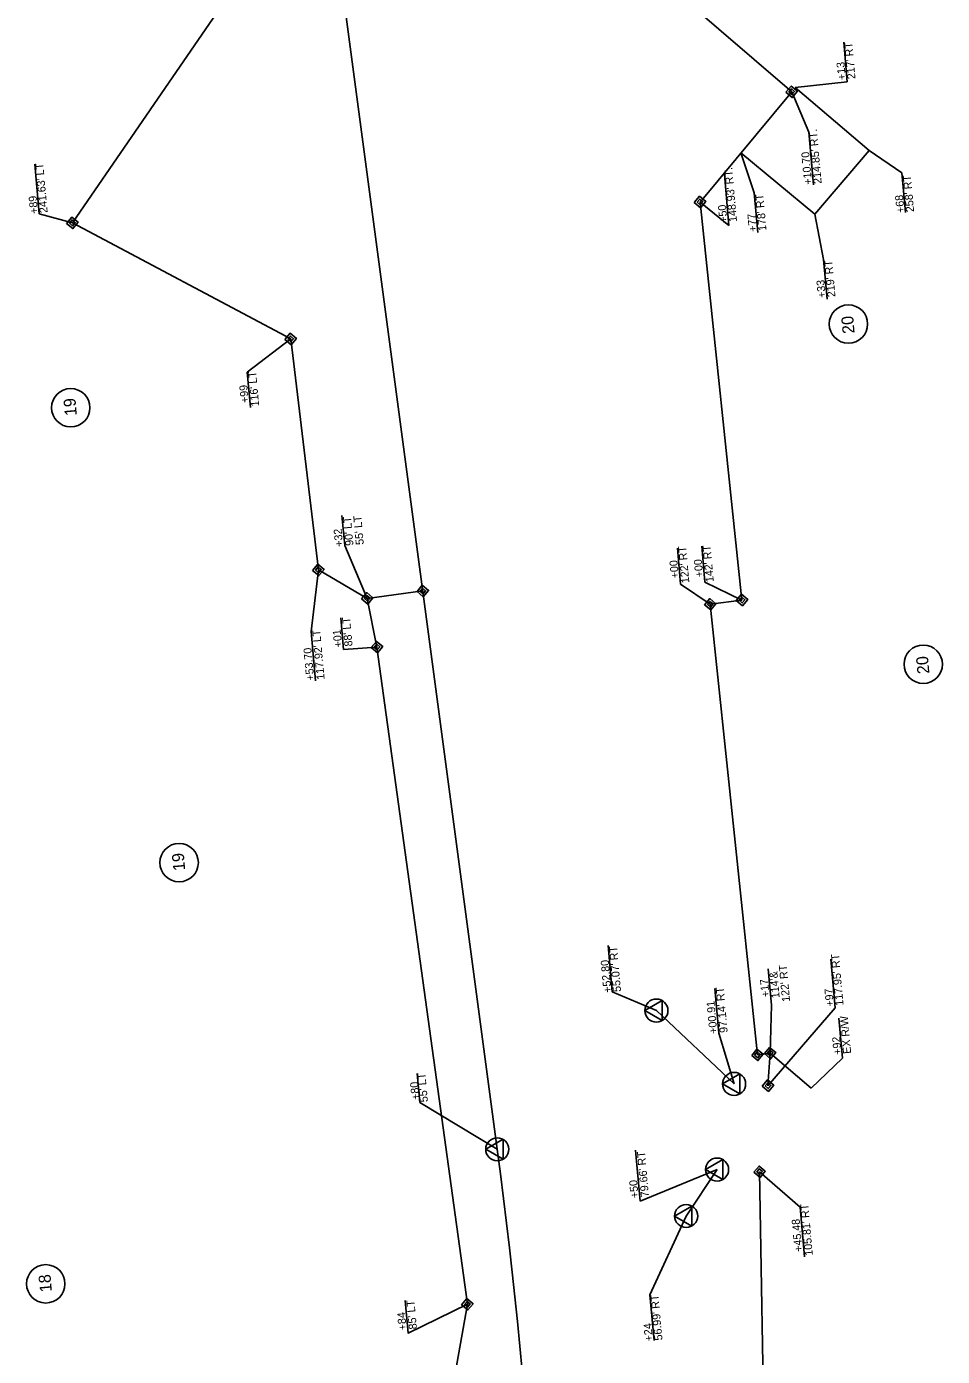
# Model space of a CAD drawing. Extents: x 1555582 to 1558054, y 687961 to 694065.
# Drawn here: x 1555788 to 1556360, y 692503 to 693334 of the extents above; entities that cross this region are included whole.
import ezdxf

# ---------------------------------------------------------------- set-up
doc = ezdxf.new("R2010")
doc.units = 0
for name, color, linetype in [('Exist Horizontal Alignment', 7, 'Continuous'), ('Exist Hydrographic FEMA Cross Section', 7, 'Continuous'), ('Exist Structure Minor Drop Inlet Text', 7, 'Continuous'), ('Prop Approach Slab', 7, 'Continuous'), ('Prop Approach Slab Hatching', 7, 'Continuous'), ('Prop Boundary Easement Temporary Drainage Label', 7, 'Continuous'), ('Prop Drainage Structure Box Reinforced Concrete', 7, 'Continuous'), ('Prop Drainage Structure Bridge', 7, 'Continuous'), ('Prop Drainage Structure Catch Basin Grate 840 03F Label', 7, 'Continuous'), ('Prop Drainage Structure Catch Basin Grate 840 03G CELL', 7, 'Continuous'), ('Prop Drainage Structure Plot Symbol 50 Scale', 7, 'Continuous'), ('Prop Plan Preparation Excavation Hatching', 7, 'Continuous'), ('Scratch_Level_3', 7, 'Continuous')]:
    doc.layers.add(name, color=color, linetype=linetype)

msp = doc.modelspace()

# ---------------------------------------------------------------- linework, layer by layer
at = {"layer": 'Exist Horizontal Alignment'}
for p, q in [((1556150.96, 692759.72), (1556153.56, 692730.83)), ((1556217.7, 692732.91), (1556220.21, 692705.02)), ((1556220.21, 692705.02), (1556229.73, 692673.27)), ((1556031.71, 692679.8), (1556033.35, 692661.64)), ((1556033.35, 692661.64), (1556081.7, 692632.42)), ((1556219.1, 692619.76), (1556171.02, 692599.96)), ((1556177.13, 692541.4), (1556179.69, 692513.01))]:
    msp.add_line(p, q, dxfattribs=at)
for points in [[(1556153.56, 692730.83), (1556181.17, 692719.14)], [(1556171.02, 692599.96), (1556168.15, 692631.83)], [(1556177.13, 692541.4), (1556199.76, 692590.71)]]:
    msp.add_lwpolyline(points, dxfattribs=at)
at = {"layer": 'Exist Hydrographic FEMA Cross Section'}
for p, q in [((1556081.7, 692632.42), (1555947.69, 693636.52)), ((1556229.73, 692673.27), (1556181.17, 692719.14)), ((1556199.76, 692590.71), (1556219.1, 692619.76))]:
    msp.add_line(p, q, dxfattribs=at)
msp.add_arc((1552867.37, 692203.31), 3242.85, 358.84759, 7.60403, dxfattribs=at)
at = {"layer": 'Exist Structure Minor Drop Inlet Text'}
for p, q in [((1556298.25, 693324.37), (1556300.48, 693299.56)), ((1556242.35, 693230.05), (1556233.92, 693255.03)), ((1556334.58, 693242.69), (1556336.82, 693217.88)), ((1556242.35, 693230.05), (1556244.58, 693205.24)), ((1556285.65, 693188.43), (1556287.88, 693163.62)), ((1556295.2, 692714.27), (1556297.43, 692689.46))]:
    msp.add_line(p, q, dxfattribs=at)
for points in [[(1556300.48, 693299.56), (1556267.91, 693295.89)], [(1556334.58, 693242.69), (1556314.16, 693256.66)], [(1556285.65, 693188.43), (1556280.13, 693216.81)], [(1556297.43, 692689.46), (1556277.96, 692670.72)]]:
    msp.add_lwpolyline(points, dxfattribs=at)
at = {"layer": 'Prop Approach Slab'}
for p, q in [((1556035.13, 692981.33), (1556000.44, 692976.7)), ((1556006.52, 692946.24), (1556000.44, 692976.7)), ((1556062.99, 692535.58), (1556006.52, 692946.24)), ((1556048.4, 692453.34), (1556062.99, 692535.58))]:
    msp.add_line(p, q, dxfattribs=at)
at = {"layer": 'Prop Approach Slab Hatching'}
for p, q in [((1556265.74, 693293.28), (1556265.74, 693293.28)), ((1556208.43, 693224.39), (1556208.43, 693224.39)), ((1555816.15, 693211.38), (1555816.15, 693211.38)), ((1555952.58, 693138.79), (1555952.58, 693138.79)), ((1555969.89, 692994.52), (1555969.89, 692994.52)), ((1556000.44, 692976.7), (1556000.44, 692976.7)), ((1556035.13, 692981.33), (1556035.13, 692981.33)), ((1556234.64, 692975.67), (1556234.64, 692975.67)), ((1556214.81, 692973.03), (1556214.81, 692973.03)), ((1556006.52, 692946.24), (1556006.52, 692946.24)), ((1556244.32, 692691.46), (1556244.32, 692691.46)), ((1556252.25, 692692.51), (1556252.25, 692692.51)), ((1556250.89, 692672.15), (1556250.89, 692672.15)), ((1556245.63, 692618.36), (1556245.63, 692618.36)), ((1556062.99, 692535.58), (1556062.99, 692535.58))]:
    msp.add_line(p, q, dxfattribs=at)
at = {"layer": 'Prop Boundary Easement Temporary Drainage Label'}
for points in [[(1555983.9, 692964.51), (1555985.67, 692944.84), (1556006.52, 692946.24)], [(1556024.17, 692537.99), (1556026.01, 692517.52), (1556062.99, 692535.58)]]:
    msp.add_lwpolyline(points, dxfattribs=at)
at = {"layer": 'Prop Drainage Structure Box Reinforced Concrete'}
for p, q in [((1556314.16, 693256.66), (1556267.91, 693295.89)), ((1556280.13, 693216.81), (1556314.16, 693256.66)), ((1556280.13, 693216.81), (1556233.92, 693255.03))]:
    msp.add_line(p, q, dxfattribs=at)
msp.add_lwpolyline([(1556277.96, 692670.72), (1556252.25, 692692.51)], dxfattribs=at)
at = {"layer": 'Prop Drainage Structure Bridge'}
for q in [(1555984.65, 693028.46), (1556000.44, 692976.7)]:
    msp.add_line((1555986.44, 693009.64), q, dxfattribs=at)
at = {"layer": 'Prop Drainage Structure Catch Basin Grate 840 03F Label'}
for p, q in [((1556301.17, 693148.14), (1556301.17, 693148.14)), ((1555815.14, 693095.83), (1555815.14, 693095.83)), ((1556347.91, 692935.53), (1556347.91, 692935.53)), ((1555882.87, 692811.56), (1555882.87, 692811.56)), ((1555799.53, 692548.33), (1555799.53, 692548.33))]:
    msp.add_line(p, q, dxfattribs=at)
for centre in [(1556301.17, 693148.14), (1555815.14, 693095.83), (1556347.91, 692935.53), (1555882.87, 692811.56), (1555799.53, 692548.33)]:
    msp.add_circle(centre, 12, dxfattribs=at)
at = {"layer": 'Prop Drainage Structure Plot Symbol 50 Scale'}
for p, q in [((1556276.33, 693267.96), (1556279.29, 693235.09)), ((1555792.7, 693247.94), (1555795.48, 693217.06)), ((1556223.64, 693241.51), (1556226.5, 693209.64)), ((1555795.48, 693217.06), (1555816.15, 693211.38)), ((1555925.45, 693118.11), (1555952.58, 693138.79)), ((1555927.44, 693095.98), (1555925.45, 693118.11)), ((1556196.29, 692985.63), (1556194.26, 693008.12)), ((1556211.52, 692986.73), (1556209.48, 693009.32)), ((1556196.29, 692985.63), (1556214.81, 692973.03)), ((1556211.52, 692986.73), (1556234.64, 692975.67)), ((1556292.83, 692720.9), (1556290.1, 692751.28)), ((1556253.12, 692722.51), (1556251.08, 692745.2)), ((1556181.17, 692719.14), (1556181.17, 692719.14)), ((1556292.83, 692720.9), (1556250.89, 692672.15)), ((1556229.73, 692673.27), (1556229.73, 692673.27)), ((1556081.7, 692632.42), (1556081.7, 692632.42)), ((1556219.1, 692619.76), (1556219.1, 692619.76)), ((1556270.99, 692596.19), (1556245.63, 692618.36)), ((1556273.77, 692565.31), (1556270.99, 692596.19)), ((1556199.76, 692590.71), (1556199.76, 692590.71))]:
    msp.add_line(p, q, dxfattribs=at)
for points in [[(1556276.33, 693267.96), (1556265.74, 693293.28)], [(1556226.5, 693209.64), (1556208.43, 693224.39)], [(1555968.11, 692925.17), (1555965.33, 692956.05), (1555969.89, 692994.52)], [(1556253.12, 692722.51), (1556252.25, 692692.51)]]:
    msp.add_lwpolyline(points, dxfattribs=at)
for points in [[(1556184.76, 692712.89), (1556173.97, 692719.15), (1556184.78, 692725.39)], [(1556233.33, 692667.02), (1556222.53, 692673.28), (1556233.34, 692679.52)], [(1556085.29, 692626.17), (1556074.5, 692632.43), (1556085.31, 692638.67)], [(1556222.69, 692613.51), (1556211.9, 692619.77), (1556222.71, 692626.01)], [(1556203.35, 692584.46), (1556192.56, 692590.72), (1556203.37, 692596.96)]]:
    msp.add_lwpolyline(points, close=True, dxfattribs=at)
for centre in [(1556181.17, 692719.14), (1556229.73, 692673.27), (1556081.7, 692632.42), (1556219.1, 692619.76), (1556199.76, 692590.71)]:
    msp.add_circle(centre, 7.2, dxfattribs=at)
at = {"layer": 'Prop Plan Preparation Excavation Hatching'}
for p, q in [((1555816.15, 693211.38), (1555929.88, 693376.88)), ((1556265.74, 693293.28), (1556177.03, 693369.51)), ((1556208.43, 693224.39), (1556265.74, 693293.28)), ((1556234.64, 692975.67), (1556208.43, 693224.39)), ((1555952.58, 693138.79), (1555816.15, 693211.38)), ((1555969.89, 692994.52), (1555952.58, 693138.79)), ((1556000.44, 692976.7), (1555969.89, 692994.52)), ((1556214.81, 692973.03), (1556234.64, 692975.67)), ((1556244.32, 692691.46), (1556214.81, 692973.03)), ((1556252.25, 692692.51), (1556244.32, 692691.46)), ((1556250.89, 692672.15), (1556252.25, 692692.51))]:
    msp.add_line(p, q, dxfattribs=at)
msp.add_lwpolyline([(1556256.69, 692093.12), (1556252.85, 692218.06), (1556250.77, 692353.77), (1556247.71, 692498.34), (1556245.63, 692618.36)], dxfattribs=at)
at = {"layer": 'Scratch_Level_3'}
for points in [[(1556262.15, 693292.96), (1556265.42, 693296.87), (1556269.32, 693293.61), (1556266.06, 693289.7)], [(1556263.95, 693293.12), (1556265.58, 693295.08), (1556267.53, 693293.44), (1556265.9, 693291.49)], [(1556204.85, 693224.07), (1556208.11, 693227.98), (1556212.02, 693224.72), (1556208.76, 693220.81)], [(1556206.64, 693224.23), (1556208.27, 693226.19), (1556210.23, 693224.55), (1556208.6, 693222.6)], [(1555812.56, 693211.06), (1555815.82, 693214.97), (1555819.73, 693211.7), (1555816.47, 693207.8)], [(1555814.35, 693211.22), (1555815.98, 693213.17), (1555817.94, 693211.54), (1555816.31, 693209.59)], [(1555948.99, 693138.47), (1555952.25, 693142.38), (1555956.16, 693139.11), (1555952.9, 693135.21)], [(1555950.78, 693138.63), (1555952.42, 693140.58), (1555954.37, 693138.95), (1555952.74, 693137)], [(1555966.31, 692994.19), (1555969.57, 692998.1), (1555973.48, 692994.84), (1555970.22, 692990.93)], [(1555968.1, 692994.36), (1555969.73, 692996.31), (1555971.68, 692994.68), (1555970.05, 692992.72)], [(1556031.55, 692981.01), (1556034.81, 692984.92), (1556038.72, 692981.65), (1556035.46, 692977.74)], [(1556033.34, 692981.17), (1556034.97, 692983.12), (1556036.93, 692981.49), (1556035.29, 692979.54)], [(1555996.86, 692976.38), (1556000.12, 692980.29), (1556004.03, 692977.02), (1556000.76, 692973.11)], [(1555998.65, 692976.54), (1556000.28, 692978.49), (1556002.23, 692976.86), (1556000.6, 692974.91)], [(1556211.23, 692972.7), (1556214.49, 692976.61), (1556218.4, 692973.35), (1556215.13, 692969.44)], [(1556213.02, 692972.87), (1556214.65, 692974.82), (1556216.6, 692973.19), (1556214.97, 692971.23)], [(1556231.05, 692975.35), (1556234.31, 692979.26), (1556238.22, 692976), (1556234.96, 692972.09)], [(1556232.84, 692975.51), (1556234.47, 692977.47), (1556236.43, 692975.83), (1556234.8, 692973.88)], [(1556002.94, 692945.91), (1556006.2, 692949.82), (1556010.11, 692946.56), (1556006.85, 692942.65)], [(1556004.73, 692946.08), (1556006.36, 692948.03), (1556008.32, 692946.4), (1556006.69, 692944.44)], [(1556240.73, 692691.13), (1556244, 692695.04), (1556247.9, 692691.78), (1556244.64, 692687.87)], [(1556242.53, 692691.29), (1556244.16, 692693.25), (1556246.11, 692691.62), (1556244.48, 692689.66)], [(1556248.66, 692692.19), (1556251.93, 692696.1), (1556255.83, 692692.84), (1556252.57, 692688.93)], [(1556250.46, 692692.35), (1556252.09, 692694.31), (1556254.04, 692692.68), (1556252.41, 692690.72)], [(1556247.3, 692671.83), (1556250.56, 692675.74), (1556254.47, 692672.48), (1556251.21, 692668.57)], [(1556249.09, 692671.99), (1556250.72, 692673.95), (1556252.68, 692672.32), (1556251.05, 692670.36)], [(1556242.04, 692618.04), (1556245.3, 692621.95), (1556249.21, 692618.68), (1556245.95, 692614.78)], [(1556243.83, 692618.2), (1556245.46, 692620.15), (1556247.42, 692618.52), (1556245.79, 692616.57)], [(1556059.4, 692535.26), (1556062.66, 692539.17), (1556066.57, 692535.91), (1556063.31, 692532)], [(1556061.19, 692535.42), (1556062.82, 692537.38), (1556064.78, 692535.75), (1556063.15, 692533.79)]]:
    msp.add_lwpolyline(points, close=True, dxfattribs=at)

# ---------------------------------------------------------------- texts
at = {"layer": 'Exist Horizontal Alignment'}
for s, p in [("55.07' RT", (1556159.08, 692730.95)), ('+52.80', (1556153.1, 692730.41)), ("97.14' RT", (1556225.72, 692705.41)), ('+00.91', (1556219.25, 692704.82)), ('+80', (1556033.15, 692663.52)), ("55' LT", (1556038.36, 692662.07)), ("79.66' RT", (1556176.54, 692602.72)), ('+50', (1556170.07, 692602.14)), ("56.99' RT", (1556184.99, 692513.16)), ('+24', (1556179.01, 692512.62))]:
    msp.add_text(s, height=5, rotation=95.14143, dxfattribs=at).set_placement(p)
at = {"layer": 'Exist Structure Minor Drop Inlet Text'}
for s, p in [("217' RT", (1556305.59, 693301.37)), ('+13', (1556299.62, 693300.83)), ("258' RT ", (1556342.24, 693218.32)), ("178' RT", (1556249.98, 693206.56)), ('+68', (1556336.26, 693217.78)), ('+77', (1556244.01, 693206.02)), ("219' RT", (1556293.08, 693165.19)), ('+33', (1556287.1, 693164.65)), ('EX R/W ', (1556302.9, 692692.27)), ('+92', (1556296.92, 692691.73))]:
    msp.add_text(s, height=5, rotation=95.14143, dxfattribs=at).set_placement(p)
at = {"layer": 'Prop Boundary Easement Temporary Drainage Label'}
for s, p in [("90' LT", (1555991.85, 693009.76)), ("55' LT", (1555998.32, 693010.35)), ('+32', (1555985.37, 693009.18)), ('+01', (1555984.78, 692946.28)), ("88' LT", (1555991.26, 692946.87)), ("85' LT", (1556031.52, 692520.1)), ('+84', (1556025.05, 692519.52))]:
    msp.add_text(s, height=5, rotation=95.14143, dxfattribs=at).set_placement(p)
at = {"layer": 'Prop Drainage Structure Catch Basin Grate 840 03G CELL'}
for s, p in [('20', (1556305.08, 693142.4)), ('19', (1555818.97, 693091.05)), ('20', (1556351.82, 692929.79)), ('19', (1555886.7, 692806.78)), ('18', (1555803.37, 692543.49))]:
    msp.add_text(s, height=7.5, rotation=95.14143, dxfattribs=at).set_placement(p)
at = {"layer": 'Prop Drainage Structure Plot Symbol 50 Scale'}
for s, p in [("214.85' RT.", (1556284.46, 693235.98)), ("241.63' LT", (1555800.71, 693217.74)), ('+10.70', (1556278.48, 693235.45)), ("148.93' RT.", (1556231.56, 693212.16)), ('+89', (1555794.73, 693217.2)), ('+50', (1556225.58, 693211.62)), ("116' LT", (1555932.9, 693096.85)), ('+99', (1555926.43, 693099.01)), ("122' RT", (1556201.77, 692986.44)), ("142' RT", (1556217.03, 692987.1)), ('+00', (1556195.22, 692989.45)), ('+00', (1556210.48, 692990.11)), ("117.92' LT", (1555973.82, 692926.09)), ('+53.70', (1555967.35, 692925.51)), ("117.95' RT", (1556298.14, 692722.35)), ("114'&", (1556258.22, 692727.03)), ("122' RT", (1556264.7, 692724.81)), ('+17', (1556251.88, 692727.74)), ('+97', (1556292.16, 692721.81)), ("105.81' RT ", (1556278.95, 692566.15)), ('+45.48', (1556272.46, 692568.57))]:
    msp.add_text(s, height=5, rotation=95.14143, dxfattribs=at).set_placement(p)

doc.saveas('drawing.dxf')
